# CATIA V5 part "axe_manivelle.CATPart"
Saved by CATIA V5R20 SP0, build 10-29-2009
Part number: axe_manivelle
Bounding box of the stored display mesh (mm): x -3 to 6, y -1 to 1, z -1 to 1
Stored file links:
  D:\Dropbox\IAO_2011\MMS_GR1\dwalter\dwalter\CATIA\axe_manivelle.CATPart
  D:\Dropbox\IAO_2011\MMS_GR1\dwalter\dwalter\CATIA\dwalter.CATProduct
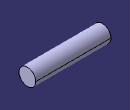
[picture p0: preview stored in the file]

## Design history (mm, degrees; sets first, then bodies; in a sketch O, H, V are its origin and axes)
Set1
  Plane1: linked copy from another document
  Line1: linked copy from another document
Body1 (main body)
  Sketch1 on Plane1, origin (0, 0, 0), H (0, 1, 0), V (0, 0, 1)
    circle A1 centre (0, 0) radius 1
    point P1 (-1, 0)
    radius A1 = 1
    coincidence: A1 P1, P1 H
  Pad1: profile Sketch1, direction (-1, 0, 0), length 3
  Pad2: profile start face of Pad1, direction along Line1, length 6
